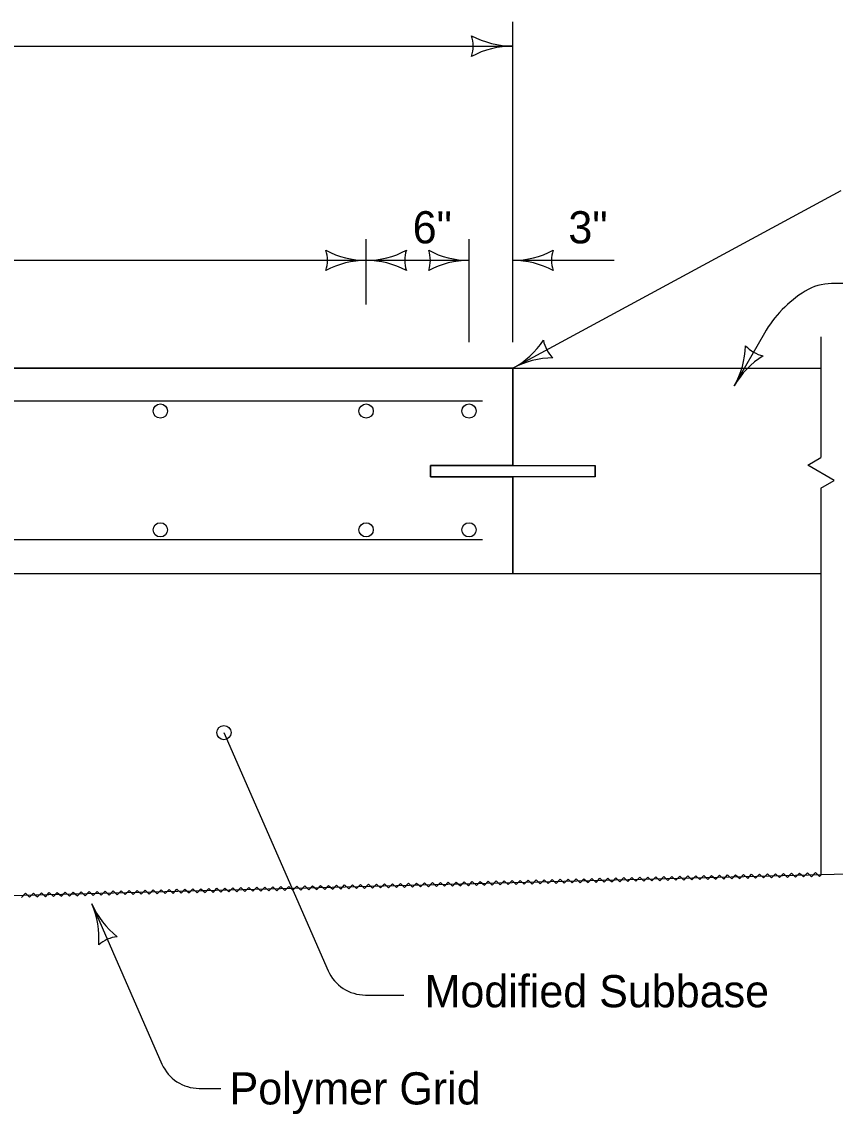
# Model space of a CAD drawing. Extents: x -2135039 to -2124495, y -2139046 to -2132546.
# Drawn here: x -2133387 to -2132982, y -2137819 to -2137276 of the extents above; entities that cross this region are included whole.
import ezdxf

# ---------------------------------------------------------------- set-up
doc = ezdxf.new("R2010")
doc.units = 0
for name, color, linetype in [('BridgeSuperStructureExisting', 7, 'Continuous'), ('dsnCellElements', 7, 'Continuous'), ('dsnStdLabel', 7, 'Continuous'), ('TC_Barrier', 7, 'Continuous')]:
    doc.layers.add(name, color=color, linetype=linetype)

msp = doc.modelspace()

# ---------------------------------------------------------------- linework, layer by layer
at = {"layer": 'BridgeSuperStructureExisting'}
for p, q in [((-2132957.53, -2137405.89), (-2132984.13, -2137405.89)), ((-2133017.58, -2137430.61), (-2133032.56, -2137456.75)), ((-2132989.46, -2137432.35), (-2132989.46, -2137492.43)), ((-2133142.62, -2137447.99), (-2133761.58, -2137447.99)), ((-2133761.58, -2137447.99), (-2133142.62, -2137447.99)), ((-2133142.61, -2137496.3), (-2133142.61, -2137447.99)), ((-2133142.61, -2137447.99), (-2133142.61, -2137496.3)), ((-2133157.68, -2137464.28), (-2133761.58, -2137464.28)), ((-2133183.54, -2137501.98), (-2133183.54, -2137496.3)), ((-2133183.54, -2137496.3), (-2133101.69, -2137496.3)), ((-2133142.61, -2137496.3), (-2133183.54, -2137496.3)), ((-2133183.54, -2137496.3), (-2133183.54, -2137501.98)), ((-2133101.69, -2137496.3), (-2133101.69, -2137501.98)), ((-2133101.69, -2137501.98), (-2133183.54, -2137501.98)), ((-2133183.54, -2137501.98), (-2133142.61, -2137501.98)), ((-2133142.61, -2137550.29), (-2133142.61, -2137501.98)), ((-2133142.61, -2137501.98), (-2133142.61, -2137550.29)), ((-2132989.46, -2137507.59), (-2132989.46, -2137699.99)), ((-2133157.68, -2137533.24), (-2133761.58, -2137533.24)), ((-2133142.61, -2137550.29), (-2133761.58, -2137550.29))]:
    msp.add_line(p, q, dxfattribs=at)
msp.add_lwpolyline([(-2132989.47, -2137507.59), (-2132982.9, -2137503.81), (-2132996.03, -2137496.21), (-2132989.47, -2137492.43)], dxfattribs=at)
for centre in [(-2133317.86, -2137469.28), (-2133215.55, -2137469.28), (-2133164.4, -2137469.28), (-2133317.86, -2137528.34), (-2133215.55, -2137528.34), (-2133164.4, -2137528.34)]:
    msp.add_circle(centre, 3.55, dxfattribs=at)
for centre, radius, start, end in [((-2133179.2, -2137287.78), 16.85, 342.2666, 17.7333), ((-2133142.62, -2137244.15), 43.63, 241.9275, 270), ((-2133142.62, -2137331.41), 43.63, 90, 118.0725), ((-2132966.04, -2137460.15), 59.4, 121.7183, 150.1783), ((-2132984.13, -2137430.89), 25, 90, 121.7183), ((-2133069.65, -2137435.49), 42.75, 330.1795, 358.2519), ((-2133014.73, -2137425.65), 16.51, 222.4461, 257.9128), ((-2132995.47, -2137478.01), 42.75, 122.107, 150.1794)]:
    msp.add_arc(centre, radius, start, end, dxfattribs=at)
at = {"layer": 'dsnCellElements'}
for centre, radius, start, end in [((-2133251.19, -2137394.34), 16.42, 342.2666, 17.7333), ((-2133215.55, -2137351.84), 42.5, 241.9275, 270), ((-2133215.55, -2137351.84), 42.5, 270, 298.0725), ((-2133179.92, -2137394.34), 16.42, 162.2666, 197.7334), ((-2133200.03, -2137394.34), 16.42, 342.2666, 17.7333), ((-2133164.4, -2137351.84), 42.5, 241.9275, 270), ((-2133142.62, -2137351.84), 42.5, 270, 298.0725), ((-2133106.98, -2137394.34), 16.42, 162.2666, 197.7334), ((-2133215.55, -2137436.84), 42.5, 90, 118.0725), ((-2133215.55, -2137436.84), 42.5, 61.9275, 90), ((-2133164.4, -2137436.84), 42.5, 90, 118.0725), ((-2133142.62, -2137436.84), 42.5, 61.9275, 90), ((-2133162.85, -2137410.61), 42.5, 298.4258, 326.4983), ((-2133111.28, -2137431.02), 16.42, 190.6925, 226.1592), ((-2133122.39, -2137485.36), 42.5, 90.3533, 118.4258), ((-2133312.99, -2137697.29), 42.5, 203.6401, 231.7126), ((-2133390.85, -2137731.37), 42.5, 355.5676, 23.6401), ((-2133337.63, -2137746.98), 16.42, 95.9068, 131.3735)]:
    msp.add_arc(centre, radius, start, end, dxfattribs=at)
at = {"layer": 'dsnStdLabel'}
for p, q in [((-2133142.62, -2137434.95), (-2133142.62, -2137275.73)), ((-2134514.26, -2137287.78), (-2133142.62, -2137287.78)), ((-2133142.62, -2137447.99), (-2132979.43, -2137359.66)), ((-2133215.55, -2137416.32), (-2133215.55, -2137383.75)), ((-2133164.4, -2137434.95), (-2133164.4, -2137383.75)), ((-2133215.55, -2137394.34), (-2133828.04, -2137394.34)), ((-2133164.4, -2137394.34), (-2133215.55, -2137394.34)), ((-2133092.22, -2137394.34), (-2133142.62, -2137394.34)), ((-2133142.61, -2137447.99), (-2132989.46, -2137447.99)), ((-2133142.61, -2137496.3), (-2133142.61, -2137447.99)), ((-2133183.54, -2137496.3), (-2133183.54, -2137501.98)), ((-2133101.69, -2137501.98), (-2133101.69, -2137496.3)), ((-2133142.61, -2137550.29), (-2133142.61, -2137501.98)), ((-2133142.61, -2137550.29), (-2133761.58, -2137550.29)), ((-2132989.46, -2137550.29), (-2133142.61, -2137550.29)), ((-2133286.23, -2137629.17), (-2133234.41, -2137747.54)), ((-2133760.84, -2137719.85), (-2132665.85, -2137691.26)), ((-2133351.92, -2137714.33), (-2133317.07, -2137793.95)), ((-2133215.9, -2137759.65), (-2133196.75, -2137759.65)), ((-2133298.56, -2137806.06), (-2133287.74, -2137806.06))]:
    msp.add_line(p, q, dxfattribs=at)
for points in [[(-2132999.11, -2137699.96), (-2132998.09, -2137700.93), (-2132996.16, -2137698.9), (-2132994.12, -2137700.82), (-2132992.19, -2137698.79), (-2132990.15, -2137700.72), (-2132989.46, -2137699.99)], [(-2133237.15, -2137706.18), (-2133236.13, -2137707.14), (-2133234.2, -2137705.11), (-2133232.17, -2137707.04), (-2133230.23, -2137705.01), (-2133228.19, -2137706.94), (-2133226.27, -2137704.9), (-2133224.23, -2137706.83), (-2133222.3, -2137704.8), (-2133220.26, -2137706.73), (-2133218.33, -2137704.7), (-2133216.29, -2137706.62), (-2133214.36, -2137704.59), (-2133212.33, -2137706.52), (-2133210.39, -2137704.49), (-2133208.36, -2137706.42), (-2133206.43, -2137704.38), (-2133204.39, -2137706.32), (-2133202.46, -2137704.28), (-2133200.43, -2137706.21), (-2133198.49, -2137704.18), (-2133196.46, -2137706.11), (-2133194.53, -2137704.07), (-2133192.49, -2137706), (-2133190.56, -2137703.97), (-2133189.54, -2137704.93)], [(-2133189.54, -2137704.93), (-2133188.52, -2137705.9), (-2133186.59, -2137703.87), (-2133184.55, -2137705.8), (-2133182.63, -2137703.76), (-2133180.59, -2137705.69), (-2133178.66, -2137703.66), (-2133176.62, -2137705.59), (-2133174.69, -2137703.56), (-2133172.65, -2137705.48), (-2133170.72, -2137703.46), (-2133168.69, -2137705.38), (-2133166.76, -2137703.35), (-2133164.72, -2137705.28), (-2133162.79, -2137703.24), (-2133160.75, -2137705.18), (-2133158.82, -2137703.14), (-2133156.78, -2137705.07), (-2133154.85, -2137703.04), (-2133152.81, -2137704.97), (-2133150.88, -2137702.93), (-2133148.85, -2137704.87), (-2133146.91, -2137702.83), (-2133144.89, -2137704.76), (-2133142.95, -2137702.73), (-2133141.94, -2137703.69)], [(-2133141.94, -2137703.69), (-2133140.92, -2137704.66), (-2133138.98, -2137702.62), (-2133136.95, -2137704.56), (-2133135.02, -2137702.52), (-2133132.98, -2137704.45), (-2133131.05, -2137702.42), (-2133129.01, -2137704.34), (-2133127.08, -2137702.32), (-2133125.04, -2137704.24), (-2133123.11, -2137702.21), (-2133121.08, -2137704.14), (-2133119.15, -2137702.1), (-2133117.11, -2137704.04), (-2133115.18, -2137702), (-2133113.14, -2137703.93), (-2133111.21, -2137701.9), (-2133109.18, -2137703.83), (-2133107.24, -2137701.8), (-2133105.21, -2137703.73), (-2133103.28, -2137701.69), (-2133101.24, -2137703.62), (-2133099.31, -2137701.59), (-2133097.27, -2137703.52), (-2133095.34, -2137701.48), (-2133094.32, -2137702.45)], [(-2133094.32, -2137702.45), (-2133093.31, -2137703.41), (-2133091.37, -2137701.38), (-2133089.34, -2137703.31), (-2133087.41, -2137701.28), (-2133085.37, -2137703.2), (-2133083.44, -2137701.18), (-2133081.41, -2137703.1), (-2133079.48, -2137701.07), (-2133077.44, -2137703), (-2133075.51, -2137700.96), (-2133073.47, -2137702.9), (-2133071.54, -2137700.86), (-2133069.5, -2137702.79), (-2133067.57, -2137700.76), (-2133065.53, -2137702.69), (-2133063.61, -2137700.66), (-2133061.57, -2137702.58), (-2133059.63, -2137700.55), (-2133057.6, -2137702.48), (-2133055.67, -2137700.45), (-2133053.63, -2137702.38), (-2133051.7, -2137700.34), (-2133049.67, -2137702.27), (-2133047.73, -2137700.24), (-2133046.72, -2137701.21)], [(-2133046.72, -2137701.21), (-2133045.7, -2137702.17), (-2133043.77, -2137700.14), (-2133041.73, -2137702.06), (-2133039.8, -2137700.04), (-2133037.77, -2137701.96), (-2133035.83, -2137699.93), (-2133033.8, -2137701.86), (-2133031.86, -2137699.83), (-2133029.83, -2137701.76), (-2133027.9, -2137699.72), (-2133025.86, -2137701.65), (-2133023.93, -2137699.61), (-2133021.9, -2137701.55), (-2133019.96, -2137699.52), (-2133017.93, -2137701.44), (-2133016, -2137699.41), (-2133013.96, -2137701.35), (-2133012.03, -2137699.31), (-2133009.99, -2137701.24), (-2133008.06, -2137699.2), (-2133006.03, -2137701.14), (-2133004.09, -2137699.1), (-2133002.06, -2137701.03), (-2133000.13, -2137699), (-2132999.11, -2137699.96)], [(-2133386.89, -2137711.08), (-2133384.96, -2137709.05), (-2133382.92, -2137710.98), (-2133380.99, -2137708.94), (-2133379.97, -2137709.91)], [(-2133379.97, -2137709.91), (-2133378.95, -2137710.88), (-2133377.02, -2137708.84), (-2133374.98, -2137710.77), (-2133373.05, -2137708.73), (-2133371.02, -2137710.67), (-2133369.09, -2137708.63), (-2133367.06, -2137710.56), (-2133365.12, -2137708.53), (-2133363.09, -2137710.46), (-2133361.15, -2137708.43), (-2133359.12, -2137710.35), (-2133357.19, -2137708.32), (-2133355.15, -2137710.25), (-2133353.22, -2137708.22), (-2133351.18, -2137710.15), (-2133349.25, -2137708.11), (-2133347.22, -2137710.04), (-2133345.28, -2137708.01), (-2133343.25, -2137709.94), (-2133341.32, -2137707.91), (-2133339.28, -2137709.84), (-2133337.35, -2137707.8), (-2133335.32, -2137709.74), (-2133333.38, -2137707.7), (-2133332.37, -2137708.67)], [(-2133332.37, -2137708.67), (-2133331.35, -2137709.63), (-2133329.42, -2137707.59), (-2133327.38, -2137709.53), (-2133325.45, -2137707.49), (-2133323.41, -2137709.42), (-2133321.48, -2137707.39), (-2133319.44, -2137709.32), (-2133317.51, -2137707.29), (-2133315.48, -2137709.21), (-2133313.54, -2137707.18), (-2133311.51, -2137709.11), (-2133309.58, -2137707.08), (-2133307.54, -2137709.01), (-2133305.61, -2137706.98), (-2133303.58, -2137708.9), (-2133301.64, -2137706.87), (-2133299.61, -2137708.8), (-2133297.68, -2137706.77), (-2133295.64, -2137708.7), (-2133293.71, -2137706.66), (-2133291.67, -2137708.6), (-2133289.74, -2137706.56), (-2133287.71, -2137708.49), (-2133285.77, -2137706.46), (-2133284.76, -2137707.42)], [(-2133284.76, -2137707.42), (-2133283.74, -2137708.39), (-2133281.81, -2137706.35), (-2133279.77, -2137708.28), (-2133277.84, -2137706.25), (-2133275.8, -2137708.18), (-2133273.87, -2137706.15), (-2133271.84, -2137708.08), (-2133269.91, -2137706.04), (-2133267.87, -2137707.97), (-2133265.94, -2137705.94), (-2133263.91, -2137707.87), (-2133261.97, -2137705.84), (-2133259.94, -2137707.76), (-2133258, -2137705.73), (-2133255.97, -2137707.66), (-2133254.03, -2137705.63), (-2133252, -2137707.56), (-2133250.07, -2137705.53), (-2133248.03, -2137707.46), (-2133246.1, -2137705.42), (-2133244.07, -2137707.35), (-2133242.14, -2137705.32), (-2133240.1, -2137707.25), (-2133238.17, -2137705.21), (-2133237.15, -2137706.18)]]:
    msp.add_lwpolyline(points, dxfattribs=at)
for centre in [(-2133215.9, -2137739.44), (-2133298.56, -2137785.85)]:
    msp.add_arc(centre, 20.21, 203.6401, 270, dxfattribs=at)
at = {"layer": 'TC_Barrier'}
msp.add_circle((-2133286.23, -2137629.17), 3.54, dxfattribs=at)

# ---------------------------------------------------------------- texts
at = {"layer": 'dsnStdLabel'}
for s, p in [('6"', (-2133192.42, -2137385.89)), ('3"', (-2133115, -2137385.89)), ('Modified Subbase', (-2133186.51, -2137765.73)), ('Polymer Grid', (-2133283.45, -2137814.06))]:
    msp.add_text(s, height=16, dxfattribs=at).set_placement(p)

doc.saveas('drawing.dxf')
